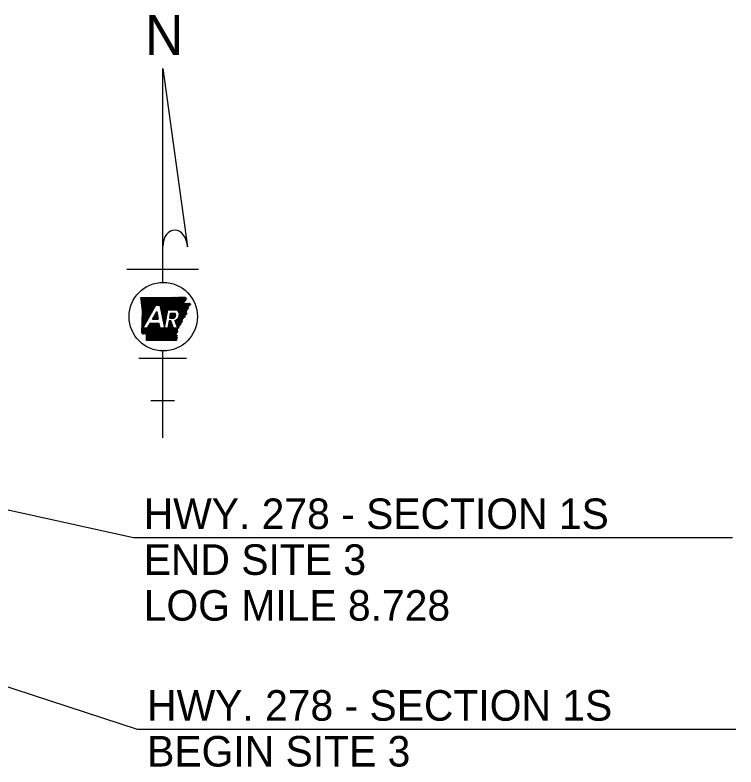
# Model space of a CAD drawing. Extents: x -2512 to 3792, y -435 to 2624.
# Drawn here: x 2465 to 3032, y 566 to 1156 of the extents above; entities that cross this region are included whole.
import ezdxf

# ---------------------------------------------------------------- set-up
doc = ezdxf.new("R2010")
doc.units = 0
doc.layers.add('R_Annotation', color=7, linetype='Continuous')
doc.layers.add('R_Draft', color=7, linetype='Continuous')

msp = doc.modelspace()

# ---------------------------------------------------------------- linework, layer by layer
at = {"layer": 'R_Annotation'}
for p, q in [((2276.46, 807.96), (2558.57, 746)), ((2558.57, 746), (3029.37, 746)), ((2182.89, 718.98), (2561.24, 595.44)), ((2561.24, 595.44), (3032.04, 595.44))]:
    msp.add_line(p, q, dxfattribs=at)
at = {"layer": 'R_Draft'}
for p, q in [((2581.38, 1114.54), (2600.79, 974.3)), ((2581.38, 946.37), (2581.38, 1114.54)), ((2553.3, 956.77), (2609.46, 956.77)), ((2564.35, 934.33), (2564.58, 934.56)), ((2564.43, 933.67), (2565.32, 934.56)), ((2564.51, 933), (2566.06, 934.56)), ((2564.59, 932.34), (2566.81, 934.56)), ((2564.67, 931.68), (2567.55, 934.56)), ((2564.76, 931.02), (2568.29, 934.56)), ((2564.84, 930.36), (2569.03, 934.56)), ((2564.92, 929.7), (2569.78, 934.55)), ((2565, 929.04), (2570.52, 934.55)), ((2565.09, 928.38), (2571.26, 934.55)), ((2565.17, 927.72), (2572.01, 934.55)), ((2565.25, 927.06), (2572.75, 934.55)), ((2565.33, 926.39), (2573.49, 934.55)), ((2565.42, 925.73), (2574.23, 934.55)), ((2565.44, 918.32), (2581.68, 934.57)), ((2565.47, 919.09), (2580.94, 934.57)), ((2565.49, 919.86), (2580.19, 934.56)), ((2565.5, 925.07), (2574.98, 934.55)), ((2565.52, 920.63), (2579.45, 934.56)), ((2565.54, 921.4), (2578.7, 934.56)), ((2565.57, 922.17), (2577.96, 934.56)), ((2565.58, 924.41), (2575.72, 934.55)), ((2565.59, 922.94), (2577.21, 934.56)), ((2565.62, 923.71), (2576.47, 934.56)), ((2576.48, 928.62), (2582.43, 934.57)), ((2577.22, 928.62), (2583.17, 934.57)), ((2577.97, 928.62), (2583.92, 934.58)), ((2578.71, 928.62), (2584.68, 934.59)), ((2579.17, 928.34), (2585.43, 934.6)), ((2579.3, 927.73), (2586.19, 934.61)), ((2579.43, 927.11), (2586.94, 934.62)), ((2579.57, 926.5), (2587.7, 934.63)), ((2579.7, 925.89), (2588.45, 934.65)), ((2579.83, 925.28), (2589.21, 934.66)), ((2579.96, 924.67), (2589.96, 934.67)), ((2580.09, 924.05), (2590.72, 934.68)), ((2580.22, 923.44), (2591.47, 934.69)), ((2580.35, 922.83), (2592.23, 934.71)), ((2580.48, 922.22), (2592.98, 934.72)), ((2580.61, 921.6), (2593.74, 934.73)), ((2580.74, 920.99), (2594.5, 934.74)), ((2580.88, 920.38), (2595.26, 934.76)), ((2586.04, 924.8), (2596.02, 934.78)), ((2586.78, 924.8), (2596.78, 934.8)), ((2587.53, 924.8), (2597.54, 934.81)), ((2588.27, 924.8), (2598.3, 934.83)), ((2589.01, 924.8), (2599.06, 934.85)), ((2589.76, 924.8), (2599.23, 934.27)), ((2590.5, 924.8), (2599.59, 933.89)), ((2565.41, 917.56), (2575.45, 927.59)), ((2565.66, 910.31), (2576.03, 928.62)), ((2576.03, 928.62), (2579.11, 928.62)), ((2591.24, 924.8), (2599.68, 933.24)), ((2591.99, 924.8), (2597.99, 930.8)), ((2592.66, 924.73), (2597.84, 929.91)), ((2593.07, 924.39), (2598.62, 929.95)), ((2593.43, 924.01), (2599.41, 929.99)), ((2593.75, 923.59), (2600.19, 930.03)), ((2594.03, 923.12), (2600.97, 930.07)), ((2594.25, 922.61), (2601.76, 930.11)), ((2594.42, 922.04), (2602.46, 930.07)), ((2594.53, 921.39), (2602.81, 929.68)), ((2602.48, 928.6), (2603.16, 929.28)), ((2565.34, 915.25), (2572.53, 922.44)), ((2565.36, 916.02), (2573.5, 924.16)), ((2565.39, 916.79), (2574.47, 925.87)), ((2573.29, 917.5), (2576.68, 923.48)), ((2574.21, 919.13), (2577.01, 921.93)), ((2575.18, 920.84), (2576.88, 922.54)), ((2576.15, 922.55), (2576.75, 923.15)), ((2581.01, 919.77), (2585.22, 923.99)), ((2581.14, 919.15), (2585.07, 923.09)), ((2581.27, 918.54), (2584.91, 922.18)), ((2585.37, 924.8), (2592.57, 924.8)), ((2586.93, 918.3), (2590.84, 922.22)), ((2587.09, 919.2), (2590.1, 922.22)), ((2587.24, 920.1), (2589.36, 922.22)), ((2587.4, 921), (2588.61, 922.22)), ((2587.56, 921.9), (2587.87, 922.22)), ((2587.61, 922.22), (2590.99, 922.22)), ((2587.68, 918.3), (2591.26, 921.89)), ((2591.31, 915.2), (2599.55, 923.44)), ((2591.51, 914.66), (2599.69, 922.84)), ((2591.71, 914.11), (2599.82, 922.23)), ((2591.91, 913.57), (2599.96, 921.63)), ((2593.73, 918.37), (2599.41, 924.04)), ((2594.37, 919.75), (2601.12, 926.5)), ((2594.53, 920.65), (2601.04, 927.16)), ((2600.29, 924.93), (2601.21, 925.84)), ((2565.24, 912.17), (2568.65, 915.59)), ((2565.26, 912.94), (2569.62, 917.3)), ((2565.29, 913.71), (2570.59, 919.02)), ((2565.31, 914.48), (2571.56, 920.73)), ((2573.29, 917.5), (2577.96, 917.5)), ((2573.33, 917.5), (2577.15, 921.32)), ((2574.07, 917.5), (2577.28, 920.7)), ((2574.81, 917.5), (2577.41, 920.09)), ((2575.56, 917.5), (2577.54, 919.48)), ((2576.3, 917.5), (2577.67, 918.87)), ((2577.04, 917.5), (2577.8, 918.25)), ((2577.79, 917.5), (2577.93, 917.64)), ((2581.4, 917.93), (2584.75, 921.28)), ((2581.53, 917.32), (2584.6, 920.38)), ((2581.66, 916.71), (2584.44, 919.48)), ((2581.79, 916.09), (2584.28, 918.58)), ((2581.92, 915.48), (2584.13, 917.68)), ((2582.05, 914.87), (2583.97, 916.78)), ((2582.19, 914.26), (2583.81, 915.88)), ((2586.13, 913.75), (2587.99, 915.6)), ((2586.29, 914.65), (2587.78, 916.13)), ((2586.45, 915.55), (2587.03, 916.13)), ((2587.8, 916.13), (2586.55, 916.13)), ((2586.93, 918.3), (2590.02, 918.3)), ((2589.95, 910.31), (2587.8, 916.13)), ((2588.42, 918.3), (2591.51, 921.39)), ((2589.16, 918.3), (2591.65, 920.79)), ((2589.91, 918.3), (2591.58, 919.98)), ((2590.85, 916.44), (2593.11, 910.31)), ((2590.9, 916.29), (2591.13, 916.51)), ((2591.11, 915.74), (2592.52, 917.16)), ((2592.11, 913.03), (2596.57, 917.49)), ((2592.31, 912.49), (2596.48, 916.66)), ((2592.51, 911.94), (2596.4, 915.83)), ((2597.42, 918.34), (2598.47, 919.39)), ((2565.07, 906.8), (2568.57, 910.31)), ((2565.08, 907.56), (2567.83, 910.31)), ((2565.11, 908.33), (2567.09, 910.31)), ((2565.13, 909.1), (2566.34, 910.31)), ((2565.16, 909.87), (2565.74, 910.45)), ((2565.19, 910.64), (2566.71, 912.16)), ((2565.21, 911.41), (2567.68, 913.88)), ((2565.35, 906.34), (2573.16, 914.15)), ((2569.22, 910.31), (2565.66, 910.31)), ((2565.79, 906.04), (2573.9, 914.15)), ((2566.32, 905.83), (2574.65, 914.15)), ((2567.21, 905.97), (2575.39, 914.15)), ((2567.96, 905.98), (2576.13, 914.15)), ((2568.54, 905.82), (2576.88, 914.15)), ((2568.57, 904.36), (2578.36, 914.15)), ((2568.57, 905.1), (2577.62, 914.15)), ((2568.57, 903.62), (2578.75, 913.8)), ((2568.57, 902.87), (2578.88, 913.19)), ((2568.57, 902.13), (2579.02, 912.57)), ((2568.58, 901.39), (2579.15, 911.96)), ((2568.59, 900.66), (2579.28, 911.35)), ((2571.39, 914.15), (2569.22, 910.31)), ((2569.33, 900.66), (2579.41, 910.74)), ((2570.06, 911.8), (2572.42, 914.15)), ((2570.07, 900.66), (2579.72, 910.31)), ((2570.82, 900.66), (2580.47, 910.31)), ((2571.03, 913.51), (2571.67, 914.15)), ((2578.68, 914.15), (2571.39, 914.15)), ((2571.56, 900.66), (2581.21, 910.31)), ((2572.3, 900.65), (2581.95, 910.31)), ((2573.04, 900.65), (2582.7, 910.31)), ((2573.78, 900.65), (2583.44, 910.31)), ((2574.53, 900.65), (2584.18, 910.31)), ((2575.27, 900.65), (2584.93, 910.31)), ((2576.01, 900.65), (2588.8, 913.43)), ((2576.75, 900.65), (2589, 912.89)), ((2577.49, 900.65), (2589.2, 912.35)), ((2578.24, 900.64), (2589.4, 911.8)), ((2578.98, 900.64), (2589.6, 911.26)), ((2585.54, 910.31), (2579.5, 910.31)), ((2579.72, 900.64), (2589.8, 910.72)), ((2580.46, 900.64), (2590.13, 910.31)), ((2581.21, 900.64), (2590.87, 910.31)), ((2581.95, 900.64), (2591.62, 910.31)), ((2582.32, 913.64), (2583.66, 914.98)), ((2582.45, 913.03), (2583.5, 914.08)), ((2582.58, 912.42), (2583.34, 913.18)), ((2582.69, 900.64), (2592.36, 910.31)), ((2582.71, 911.81), (2583.18, 912.28)), ((2582.84, 911.2), (2583.03, 911.38)), ((2583.43, 900.64), (2592.61, 909.81)), ((2585.66, 911.04), (2588.59, 913.98)), ((2585.82, 911.95), (2588.39, 914.52)), ((2585.98, 912.85), (2588.19, 915.06)), ((2593.11, 910.31), (2589.95, 910.31)), ((2592.71, 911.4), (2594.99, 913.68)), ((2592.91, 910.86), (2594.67, 912.62)), ((2584.17, 900.63), (2592.64, 909.1)), ((2584.92, 900.63), (2592.68, 908.39)), ((2585.66, 900.63), (2592.71, 907.68)), ((2586.4, 900.63), (2591.49, 905.72)), ((2587.14, 900.63), (2591.72, 905.2)), ((2587.88, 900.63), (2591.95, 904.69)), ((2588.63, 900.63), (2592.18, 904.18)), ((2589.37, 900.63), (2592.41, 903.66)), ((2590.11, 900.62), (2592.6, 903.11)), ((2590.85, 900.62), (2592.26, 902.03)), ((2591.59, 900.62), (2591.92, 900.95)), ((2581.38, 824.33), (2581.38, 892.58)), ((2562.66, 886.78), (2600.1, 886.78)), ((2572.02, 853.53), (2590.74, 853.53))]:
    msp.add_line(p, q, dxfattribs=at)
for points in [[(2564.31, 934.55), (2574.57, 934.55), (2583.57, 934.57), (2594.19, 934.73), (2599.11, 934.85)], [(2565.45, 918.62), (2565.63, 924.02), (2564.31, 934.55)], [(2564.32, 934.56), (2574.57, 934.55), (2583.57, 934.57), (2594.19, 934.74), (2599.11, 934.85)], [(2565.06, 906.81), (2565.63, 924.02), (2564.32, 934.56)], [(2579.11, 928.62), (2582.93, 910.8), (2585.37, 924.8)], [(2602.33, 930.14), (2603.22, 929.21), (2601.01, 927.39), (2601.24, 925.56), (2599.35, 924.31), (2600, 921.48), (2598.53, 920.15), (2598.4, 918.7), (2596.62, 918.06), (2596.35, 915.32), (2595.07, 913.95), (2594.45, 911.89), (2592.59, 910.19), (2592.73, 907.18), (2591.47, 905.76), (2592.62, 903.18), (2591.82, 900.62)], [(2597.59, 929.9), (2602.4, 930.14)], [(2597.59, 929.9), (2602.4, 930.14)], [(2576.68, 923.48), (2577.96, 917.5)], [(2586.93, 918.3), (2587.61, 922.22)], [(2565.06, 906.81), (2565.45, 918.62)], [(2586.55, 916.13), (2585.54, 910.31)], [(2579.5, 910.31), (2578.68, 914.15)], [(2591.82, 900.62), (2568.58, 900.66), (2568.57, 905.79)], [(2591.82, 900.62), (2568.58, 900.66), (2568.57, 905.79)]]:
    msp.add_lwpolyline(points, dxfattribs=at)
for centre, major_axis, ratio, start_param, end_param in [((2591.08, 974), (-0.41, 13.48), 0.719778, 4.712385, 7.768526), ((2589.28, 920.57), (-2.38, 0), 0.999987, 1.887169, 3.90762), ((2589.89, 921), (-4.65, 0), 0.999987, 1.777838, 4.099264)]:
    msp.add_ellipse(centre, major_axis=major_axis, ratio=ratio, start_param=start_param, end_param=end_param, dxfattribs=at)
msp.add_ellipse((2581.82, 919.48), major_axis=(26.9, 0), ratio=0.999976, dxfattribs=at)
for points in [[(2599.11, 934.85), (2599.14, 934.57), (2599.23, 934.43), (2599.24, 934.16), (2599.35, 934.04), (2599.54, 933.93), (2599.69, 933.75), (2599.74, 933.53), (2599.68, 933.31), (2599.67, 933.06), (2599.65, 932.84), (2599.61, 932.65), (2599.46, 932.49), (2599.31, 932.38), (2599.18, 932.25), (2599.08, 932.1), (2598.92, 931.95), (2598.75, 931.79), (2598.62, 931.65), (2598.49, 931.48), (2598.42, 931.28), (2598.28, 931.14), (2598.16, 931.01), (2598.01, 930.84), (2597.94, 930.67), (2597.79, 930.47), (2597.76, 930.29), (2597.66, 930.13), (2597.66, 930.11)], [(2599.11, 934.85), (2599.14, 934.57), (2599.23, 934.42), (2599.24, 934.16), (2599.35, 934.04), (2599.53, 933.93), (2599.7, 933.75), (2599.74, 933.53), (2599.69, 933.31), (2599.67, 933.06), (2599.65, 932.85), (2599.61, 932.65), (2599.46, 932.49), (2599.31, 932.38), (2599.18, 932.24), (2599.08, 932.1), (2598.92, 931.95), (2598.75, 931.79), (2598.62, 931.65), (2598.49, 931.48), (2598.42, 931.28), (2598.28, 931.14), (2598.16, 931.01), (2598.01, 930.84), (2597.94, 930.67), (2597.79, 930.47), (2597.76, 930.28), (2597.66, 930.13), (2597.66, 930.11)], [(2602.33, 930.14), (2602.4, 930.14), (2602.61, 929.92), (2602.71, 929.72), (2602.85, 929.62), (2603.01, 929.56), (2603.13, 929.42), (2603.21, 929.26), (2603.17, 929.11), (2602.99, 929.1), (2602.79, 929.07), (2602.6, 929.08), (2602.45, 928.95), (2602.59, 928.78), (2602.77, 928.62), (2602.83, 928.45), (2602.72, 928.29), (2602.52, 928.2), (2602.32, 928.12), (2602.15, 927.97), (2602.06, 927.82), (2601.87, 927.76), (2601.67, 927.7), (2601.49, 927.68), (2601.29, 927.64), (2601.09, 927.55), (2601.01, 927.39), (2601.03, 927.15), (2601.03, 926.9), (2601.23, 926.82), (2601.42, 926.81), (2601.6, 926.72), (2601.57, 926.58), (2601.44, 926.4), (2601.29, 926.26), (2601.13, 926.19), (2600.98, 926.06), (2601.03, 925.92), (2601.16, 925.84), (2601.26, 925.69), (2601.24, 925.56), (2601.09, 925.46), (2600.93, 925.5), (2600.8, 925.66), (2600.67, 925.71), (2600.55, 925.77), (2600.41, 925.69), (2600.41, 925.5), (2600.36, 925.31), (2600.4, 925.16), (2600.45, 924.96), (2600.45, 924.81), (2600.4, 924.59), (2600.29, 924.36), (2600.17, 924.3), (2600.11, 924.54), (2600.09, 924.73), (2600.01, 924.85), (2599.91, 924.85), (2599.78, 924.76), (2599.64, 924.61), (2599.45, 924.45), (2599.34, 924.3), (2599.4, 924.1), (2599.54, 924.05), (2599.65, 924.09), (2599.71, 924.21), (2599.81, 924.23), (2599.91, 924.03)], [(2599.91, 924.03), (2599.94, 923.85), (2599.83, 923.66), (2599.79, 923.46), (2599.81, 923.26), (2599.61, 923.16), (2599.43, 923.03), (2599.54, 922.88), (2599.73, 922.74), (2599.91, 922.63), (2600.03, 922.52), (2600.06, 922.26), (2600.1, 922.1), (2600.16, 921.87), (2600.19, 921.71), (2600.07, 921.52), (2599.94, 921.48), (2599.8, 921.52), (2599.64, 921.54), (2599.5, 921.42), (2599.41, 921.23), (2599.31, 921.06), (2599.24, 920.9), (2599.17, 920.74), (2599.03, 920.55), (2598.86, 920.52), (2598.66, 920.47), (2598.54, 920.33), (2598.56, 920.09), (2598.67, 919.94), (2598.76, 919.74), (2598.82, 919.57), (2598.79, 919.35), (2598.71, 919.19), (2598.59, 919.09), (2598.54, 918.9), (2598.45, 918.74), (2598.38, 918.69), (2598.23, 918.7), (2598.06, 918.73), (2597.92, 918.72), (2597.79, 918.65), (2597.66, 918.7), (2597.52, 918.85), (2597.4, 918.96), (2597.27, 919.01), (2597.14, 918.94), (2597.12, 918.73), (2597.18, 918.51), (2597.24, 918.22), (2597.18, 918.04), (2597.16, 917.75)], [(2597.16, 917.75), (2596.94, 917.58), (2596.84, 917.41), (2596.28, 917.46), (2596.29, 917.26), (2596.09, 917.16), (2595.91, 917.03), (2596.01, 916.87), (2596.21, 916.73), (2596.4, 916.63), (2596.51, 916.52), (2596.55, 916.26), (2596.58, 916.09), (2596.64, 915.86), (2596.67, 915.71), (2596.55, 915.52), (2596.42, 915.48), (2596.28, 915.52), (2596.12, 915.54), (2595.98, 915.41), (2595.89, 915.23), (2595.8, 915.05), (2595.72, 914.9), (2595.65, 914.74), (2595.52, 914.54), (2595.35, 914.52), (2595.14, 914.46), (2595.02, 914.33), (2595.04, 914.09), (2595.15, 913.93), (2595.24, 913.73), (2595.3, 913.56), (2595.28, 913.35), (2595.19, 913.19), (2595.07, 913.09), (2595.02, 912.89), (2594.94, 912.74), (2594.86, 912.69), (2594.71, 912.7), (2594.55, 912.73), (2594.41, 912.72), (2594.27, 912.65), (2594.14, 912.7), (2594, 912.85), (2593.88, 912.96), (2593.76, 913.01), (2593.62, 912.94), (2593.6, 912.73), (2593.67, 912.51), (2593.72, 912.22), (2593.67, 912.04), (2593.65, 911.75)], [(2593.65, 911.75), (2593.63, 911.74), (2593.52, 911.6), (2593.58, 911.37), (2593.83, 911.28), (2593.94, 911.07), (2593.94, 910.88), (2593.87, 910.62), (2593.75, 910.5), (2593.53, 910.44), (2593.36, 910.41), (2593.33, 910.12), (2593.25, 909.98), (2593.12, 909.93), (2592.93, 910.03), (2592.82, 910.08), (2592.68, 910.14), (2592.5, 910.24), (2592.36, 910.22), (2592.4, 909.95), (2592.42, 909.93), (2592.57, 909.72), (2592.72, 909.56), (2592.79, 909.36)], [(2593.65, 911.75), (2593.63, 911.74), (2593.52, 911.6), (2593.58, 911.37), (2593.83, 911.28), (2593.94, 911.07), (2593.94, 910.88), (2593.87, 910.62), (2593.75, 910.5), (2593.53, 910.44), (2593.36, 910.41), (2593.33, 910.12), (2593.25, 909.98), (2593.12, 909.93), (2592.93, 910.03), (2592.82, 910.08), (2592.68, 910.14), (2592.5, 910.24), (2592.36, 910.22), (2592.4, 909.95), (2592.42, 909.93), (2592.57, 909.72), (2592.72, 909.56), (2592.79, 909.36)], [(2568.57, 905.79), (2568.59, 905.78), (2568.47, 905.86), (2568.31, 905.94), (2568.12, 905.95), (2567.88, 905.99), (2567.69, 906), (2567.49, 906.14), (2567.27, 906), (2567.03, 905.9), (2566.89, 906.02), (2566.71, 905.94), (2566.58, 905.98), (2566.36, 905.82), (2566.15, 905.88), (2566, 905.84), (2565.81, 905.84), (2565.77, 906.06), (2565.58, 906.09), (2565.43, 906.18), (2565.32, 906.4), (2565.24, 906.57), (2565.06, 906.81)], [(2568.57, 905.79), (2568.59, 905.78), (2568.47, 905.86), (2568.31, 905.94), (2568.12, 905.96), (2567.89, 905.99), (2567.69, 906.01), (2567.49, 906.14), (2567.27, 906), (2567.03, 905.9), (2566.89, 906.01), (2566.71, 905.94), (2566.58, 905.97), (2566.36, 905.82), (2566.15, 905.88), (2566, 905.84), (2565.81, 905.84), (2565.77, 906.06), (2565.58, 906.09), (2565.43, 906.18), (2565.32, 906.4), (2565.24, 906.57), (2565.06, 906.81)], [(2592.79, 909.36), (2592.73, 909.21), (2592.66, 908.96), (2592.68, 908.75), (2592.78, 908.56), (2592.92, 908.46), (2593.09, 908.32), (2593.08, 908.09), (2592.98, 908.01), (2592.76, 908.07), (2592.59, 908.15), (2592.44, 908.1), (2592.25, 908.01), (2592.1, 907.98), (2592.11, 907.68), (2592.3, 907.46), (2592.47, 907.46), (2592.67, 907.44), (2592.74, 907.21), (2592.63, 907.02), (2592.44, 906.93), (2592.2, 907.04), (2592.03, 907.16), (2591.85, 907.27), (2591.64, 907.33), (2591.52, 907.31), (2591.46, 907.04), (2591.56, 906.8), (2591.72, 906.63), (2591.88, 906.42), (2591.85, 906.26), (2591.74, 906.22), (2591.54, 906.17), (2591.42, 906.11), (2591.39, 906.06), (2591.45, 905.84), (2591.5, 905.61), (2591.5, 905.43), (2591.43, 905.27), (2591.33, 905.02), (2591.34, 904.85), (2591.42, 904.77), (2591.51, 904.79), (2591.64, 904.88), (2591.72, 904.99), (2591.79, 905.11), (2591.92, 905.22), (2592.09, 905.12), (2592.13, 904.93), (2592.03, 904.76), (2591.9, 904.68), (2591.73, 904.62), (2591.61, 904.48), (2591.64, 904.31), (2591.74, 904.22), (2591.98, 904.27), (2592.13, 904.34), (2592.22, 904.42), (2592.33, 904.53), (2592.38, 904.65), (2592.47, 904.76), (2592.62, 904.79), (2592.69, 904.7), (2592.66, 904.48), (2592.57, 904.27), (2592.45, 904.1), (2592.32, 903.99), (2592.15, 903.72), (2592.18, 903.48), (2592.25, 903.28), (2592.33, 903.13), (2592.49, 903.16), (2592.66, 903.18), (2592.76, 903.1), (2592.75, 902.92), (2592.62, 902.75), (2592.5, 902.59), (2592.44, 902.36), (2592.46, 902.2), (2592.46, 902.06), (2592.41, 901.89), (2592.32, 901.81), (2592.09, 901.81), (2591.84, 901.84), (2591.71, 901.76), (2591.73, 901.55), (2591.88, 901.39), (2591.98, 901.31), (2592.13, 901.13), (2592.19, 900.98), (2592.17, 900.86), (2592.08, 900.74), (2591.82, 900.62)], [(2592.79, 909.36), (2592.73, 909.21), (2592.66, 908.96), (2592.68, 908.75), (2592.78, 908.56), (2592.92, 908.46), (2593.09, 908.32), (2593.08, 908.09), (2592.98, 908.01), (2592.76, 908.07), (2592.59, 908.15), (2592.44, 908.1), (2592.25, 908.01), (2592.1, 907.98), (2592.11, 907.68), (2592.3, 907.46), (2592.47, 907.46), (2592.67, 907.44), (2592.74, 907.21), (2592.63, 907.02), (2592.44, 906.93), (2592.2, 907.04), (2592.03, 907.16), (2591.85, 907.27), (2591.64, 907.33), (2591.52, 907.31), (2591.46, 907.04), (2591.56, 906.8), (2591.72, 906.63), (2591.88, 906.42), (2591.85, 906.26), (2591.74, 906.22), (2591.54, 906.17), (2591.42, 906.11), (2591.39, 906.06), (2591.45, 905.84), (2591.5, 905.61), (2591.5, 905.43), (2591.43, 905.27), (2591.33, 905.02), (2591.34, 904.85), (2591.42, 904.77), (2591.51, 904.79), (2591.64, 904.88), (2591.72, 904.99), (2591.79, 905.11), (2591.92, 905.22), (2592.09, 905.12), (2592.13, 904.93), (2592.03, 904.76), (2591.9, 904.68), (2591.73, 904.62), (2591.61, 904.48), (2591.64, 904.31), (2591.74, 904.22), (2591.98, 904.27), (2592.13, 904.34), (2592.22, 904.42), (2592.33, 904.53), (2592.38, 904.65), (2592.47, 904.76), (2592.62, 904.79), (2592.69, 904.7), (2592.66, 904.48), (2592.57, 904.27), (2592.45, 904.1), (2592.32, 903.99), (2592.15, 903.72), (2592.18, 903.48), (2592.25, 903.28), (2592.33, 903.13), (2592.49, 903.16), (2592.66, 903.18), (2592.76, 903.1), (2592.75, 902.92), (2592.62, 902.75), (2592.5, 902.59), (2592.44, 902.36), (2592.46, 902.2), (2592.46, 902.06), (2592.41, 901.89), (2592.32, 901.81), (2592.09, 901.81), (2591.84, 901.84), (2591.71, 901.76), (2591.73, 901.55), (2591.88, 901.39), (2591.98, 901.31), (2592.13, 901.13), (2592.19, 900.98), (2592.17, 900.86), (2592.08, 900.74), (2591.82, 900.62)]]:
    msp.add_spline(points, degree=3, dxfattribs=at)

# ---------------------------------------------------------------- texts
at = {"layer": 'R_Annotation'}
for s, p in [('HWY. 278 - SECTION 1S', (2566.5, 752.63)), ('END SITE 3', (2566.5, 716.63)), ('LOG MILE 8.728', (2566.5, 680.63)), ('HWY. 278 - SECTION 1S', (2569.17, 602.06)), ('BEGIN SITE 3', (2569.17, 566.06))]:
    msp.add_text(s, height=24, dxfattribs=at).set_placement(p)
at = {"layer": 'R_Draft'}
for s, height, p in [('N', 31.3, (2567.43, 1125.12)), ('STS 10-03-17', 0.7778, (2579.25, 892.8))]:
    msp.add_text(s, height=height, dxfattribs=at).set_placement(p)

doc.saveas('drawing.dxf')
